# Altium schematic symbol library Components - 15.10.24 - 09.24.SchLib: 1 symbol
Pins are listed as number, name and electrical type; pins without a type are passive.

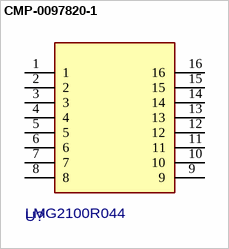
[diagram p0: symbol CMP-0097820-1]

## CMP-0097820-1
designator U?, comment LMG2100R044
Manufacturer: Texas Instruments; SizeZ_mm: 0.89mm; Standoff Height: 0mm
footprint RAR0016A-MFG
pins: 1, 2, 3, 4, 5, 6, 7, 8, 9, 10, 11, 12, 13, 14, 15, 16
